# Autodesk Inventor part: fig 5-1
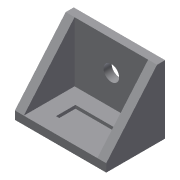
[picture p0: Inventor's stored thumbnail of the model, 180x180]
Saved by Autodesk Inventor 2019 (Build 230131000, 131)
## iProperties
Created: 2012-07
Part Number: fig 5-1
Material: Generic
Document SubType Name: Modeling
Designer: CADCIM
Density: 1 g/cm^3
Appearance: Default
Author: CADCIM
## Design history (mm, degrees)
sketch "Sketch1"
  geometry: L1 (-14.1, 7.837)-(14.1, 7.837); L2 (14.1, 7.837)-(14.1, -7.837); L3 (14.1, -7.837)-(-14.1, -7.837); L4 (-14.1, -7.837)-(-14.1, 7.837); L5 (-14.1, 7.837)-(14.1, -7.837); L6 (14.1, 7.837)-(-14.1, -7.837); 1 further point
  constraints: 12 end point, 2 midpoint, 2 parallel, 1 horizontal, 1 perpendicular
extrude "Extrusion1" new body sketch "Sketch1" distance "d0" = 2.5; taper "d1" = 0 deg
sketch "Sketch2"
  geometry: L1 (0, -20.969)-(28.201, -20.969); L2 (28.201, -20.969)-(28.201, 0); L3 (28.201, 0)-(0, 0); L4 (0, 0)-(0, -20.969); L5 (0, -20.969)-(28.201, 0); L6 (28.201, -20.969)-(0, 0); 1 further point
  constraints: 12 end point, 2 midpoint, 2 parallel, 1 horizontal, 1 perpendicular
extrude "Extrusion2" join sketch "Sketch2" distance "d2" = 2.5; taper "d3" = 0 deg
sketch "Sketch3"
  geometry: L1 (-6.24, 3)-(6.24, 3); L2 (6.24, 3)-(6.24, -3); L3 (6.24, -3)-(-6.24, -3); L4 (-6.24, -3)-(-6.24, 3); L5 (-6.24, 3)-(6.24, -3); L6 (6.24, 3)-(-6.24, -3); 1 further point
  constraints: 12 end point, 2 midpoint, 2 parallel, 1 horizontal, 1 perpendicular
extrude "Extrusion3" cut sketch "Sketch3" distance "d4" = 1; taper "d5" = 0 deg
sketch "Sketch4"
  geometry: L1 (2.5, 18.174)-(2.5, 0) reference; L2 (-18.469, 15.674)-(0, 15.674) reference; L3 (-18.469, 15.674)-(0, 0); L4 (-18.469, 15.674)-(0, 15.674); L5 (0, 0)-(0, 15.674)
  constraints: 6 end point, 1 collinear, 1 parallel
extrude "Extrusion4" join sketch "Sketch4" distance "d6" = 2.75; taper "d7" = 0 deg
mirror "Mirror1"
sketch "Sketch5"
  geometry: C1 r 2.409 at (14.1, 11.735)
  constraints: 1 centre point
extrude "Extrusion5" cut sketch "Sketch5" distance "d8" = 2.75; taper "d9" = 0 deg
body "Solid1"
